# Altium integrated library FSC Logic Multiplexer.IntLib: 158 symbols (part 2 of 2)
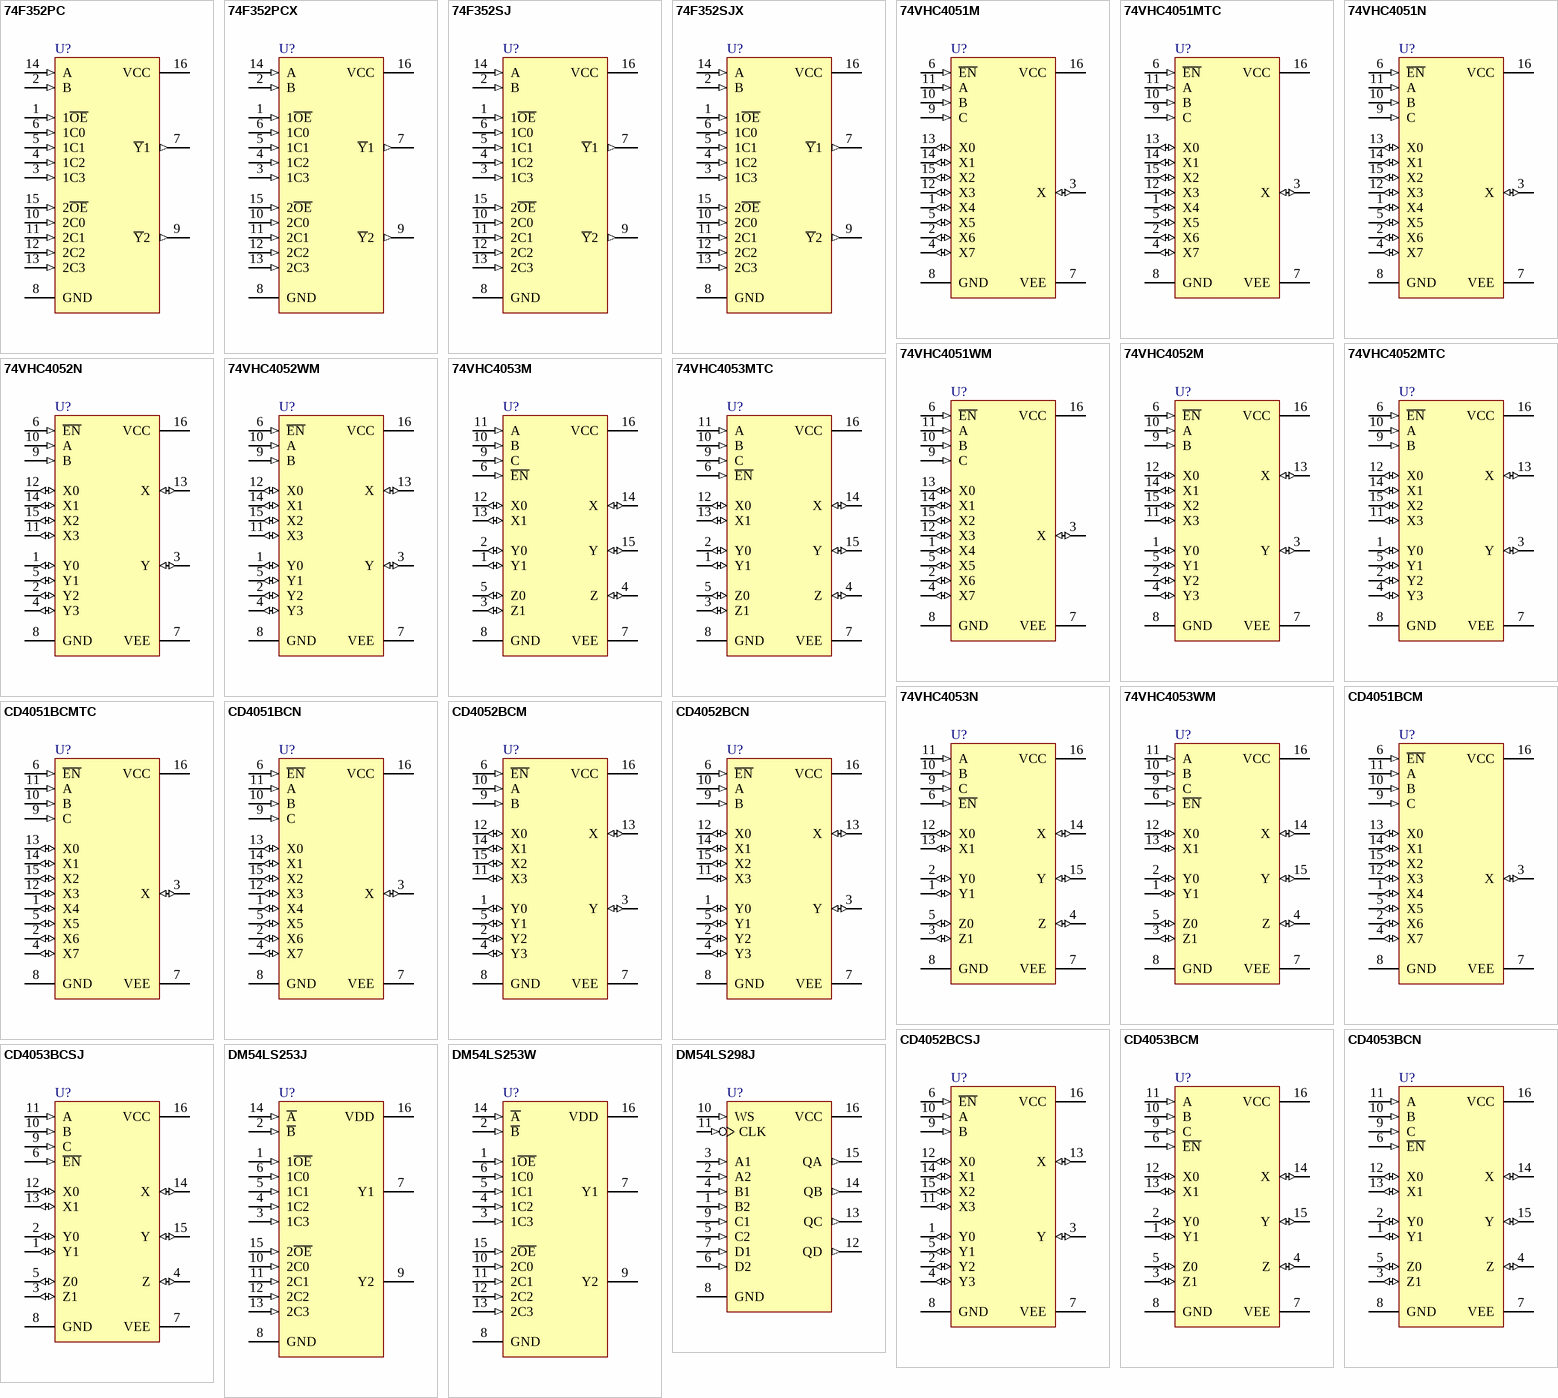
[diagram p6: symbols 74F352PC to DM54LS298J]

## DM54LS253W
designator U?
3-State Data Selector/Multiplexer; Note: Generic simulation model provided.
footprint W16A (DFP; 16 Leads; Body 9.9 x 7.6 mm (LxW max); Pitch 1.27 mm)
3D model W16A (DFP; 16 Leads; Body 9.9 x 7.6 mm (LxW max); Pitch 1.27 mm)
simulation model 74LS253 (SIMCODE)
signal-integrity model DM54LS253W
pins: 1 1~{OE} (in), 2 ~{B} (in), 3 1C3 (in), 4 1C2 (in), 5 1C1 (in), 6 1C0 (in), 7 Y1 (hiz), 8 GND (power), 9 Y2 (hiz), 10 2C0 (in), 11 2C1 (in), 12 2C2 (in), 13 2C3 (in), 14 ~{A} (in), 15 2~{OE} (in), 16 VDD (power)

## DM54LS298J
designator U?
Quad 2-Port Register Multiplexer with Storage; Note: Generic simulation model provided.
footprint J16A (DIP, 16-Leads, Row Spacing 7.62mm, Pitch 2.54mm, Body 19.56x6.73mm)
3D model N16E (CerDIP, 16-Pin, Row Spacing 7.62 mm, Pitch 2.54 mm)
simulation model 74LS298 (SIMCODE)
signal-integrity model DM54LS298J
pins: 1 B2 (in), 2 A2 (in), 3 A1 (in), 4 B1 (in), 5 C2 (in), 6 D2 (in), 7 D1 (in), 8 GND (power), 9 C1 (in), 10 WS (in), 11 CLK (in), 12 QD (out), 13 QC (out), 14 QB (out), 15 QA (out), 16 VCC (power)

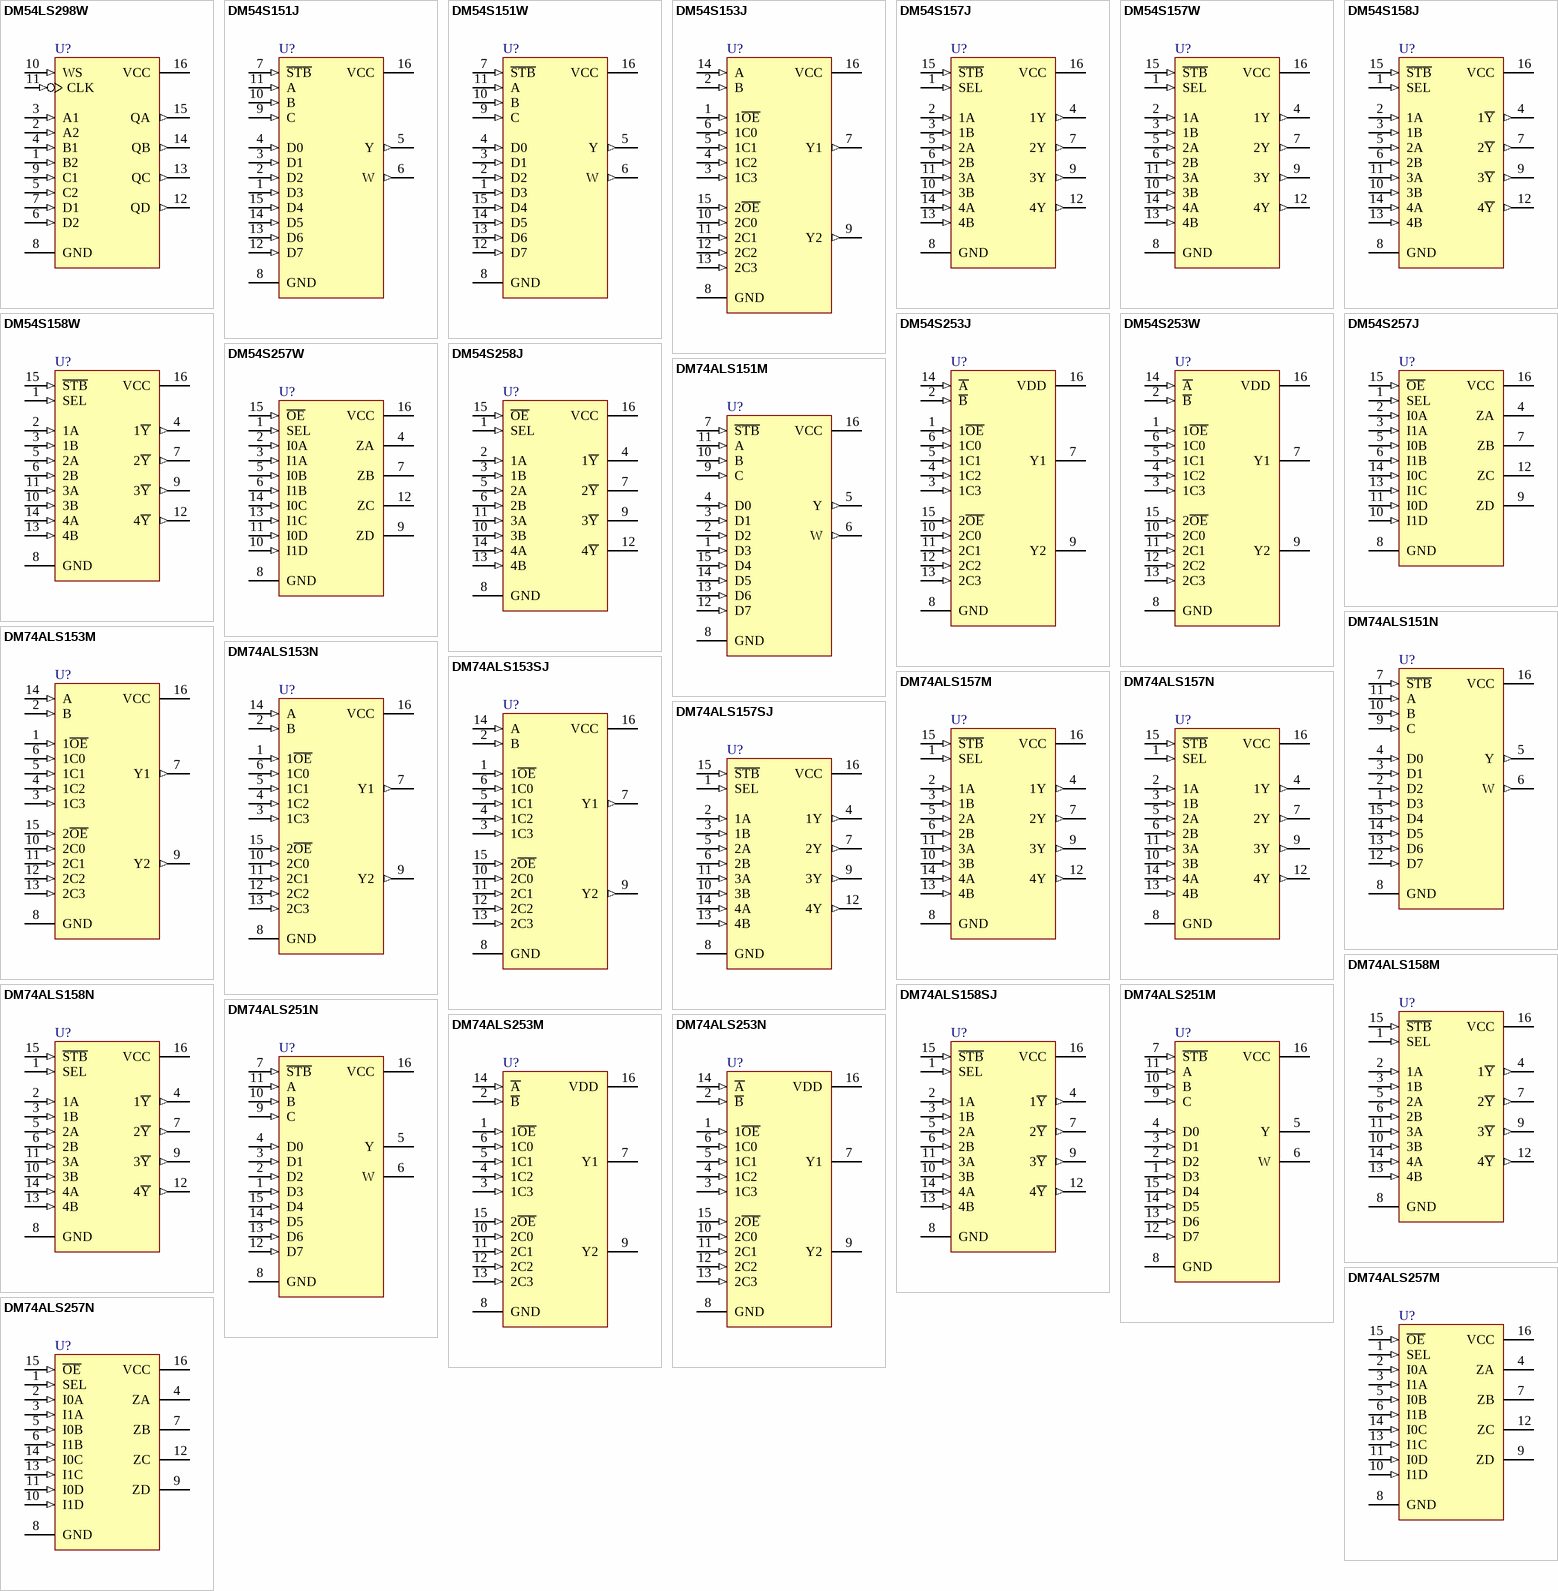
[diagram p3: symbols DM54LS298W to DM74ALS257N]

## DM54LS298W
designator U?
Quad 2-Port Register Multiplexer with Storage; Note: Generic simulation model provided.
footprint W16A (DFP; 16 Leads; Body 9.9 x 7.6 mm (LxW max); Pitch 1.27 mm)
3D model W16A (DFP; 16 Leads; Body 9.9 x 7.6 mm (LxW max); Pitch 1.27 mm)
simulation model 74LS298 (SIMCODE)
signal-integrity model DM54LS298W
pins: 1 B2 (in), 2 A2 (in), 3 A1 (in), 4 B1 (in), 5 C2 (in), 6 D2 (in), 7 D1 (in), 8 GND (power), 9 C1 (in), 10 WS (in), 11 CLK (in), 12 QD (out), 13 QC (out), 14 QB (out), 15 QA (out), 16 VCC (power)

## DM54S151J
designator U?
1 of 8 Data Selector/Multiplexer with Complementary Outputs
footprint J16A (DIP, 16-Leads, Row Spacing 7.62mm, Pitch 2.54mm, Body 19.56x6.73mm)
3D model N16E (CerDIP, 16-Pin, Row Spacing 7.62 mm, Pitch 2.54 mm)
signal-integrity model DM54S151J
pins: 1 D3 (in), 2 D2 (in), 3 D1 (in), 4 D0 (in), 5 Y (out), 6 W (out), 7 ~{STB} (in), 8 GND (power), 9 C (in), 10 B (in), 11 A (in), 12 D7 (in), 13 D6 (in), 14 D5 (in), 15 D4 (in), 16 VCC (power)

## DM54S151W
designator U?
1 of 8 Data Selector/Multiplexer with Complementary Outputs
footprint W16A (DFP; 16 Leads; Body 9.9 x 7.6 mm (LxW max); Pitch 1.27 mm)
3D model W16A (DFP; 16 Leads; Body 9.9 x 7.6 mm (LxW max); Pitch 1.27 mm)
signal-integrity model DM54S151W
pins: 1 D3 (in), 2 D2 (in), 3 D1 (in), 4 D0 (in), 5 Y (out), 6 W (out), 7 ~{STB} (in), 8 GND (power), 9 C (in), 10 B (in), 11 A (in), 12 D7 (in), 13 D6 (in), 14 D5 (in), 15 D4 (in), 16 VCC (power)

## DM54S153J
designator U?
Dual 1 of 4 Line Data Selector/Multiplexer
footprint J16A (DIP, 16-Leads, Row Spacing 7.62mm, Pitch 2.54mm, Body 19.56x6.73mm)
3D model N16E (CerDIP, 16-Pin, Row Spacing 7.62 mm, Pitch 2.54 mm)
signal-integrity model DM54S153J
pins: 1 1~{OE} (in), 2 B (in), 3 1C3 (in), 4 1C2 (in), 5 1C1 (in), 6 1C0 (in), 7 Y1 (out), 8 GND (power), 9 Y2 (out), 10 2C0 (in), 11 2C1 (in), 12 2C2 (in), 13 2C3 (in), 14 A (in), 15 2~{OE} (in), 16 VCC (power)

## DM54S157J
designator U?
Quad 1 of 2 Line Data Selector/Multiplexer; Note: Generic simulation model provided.
footprint J16A (DIP, 16-Leads, Row Spacing 7.62mm, Pitch 2.54mm, Body 19.56x6.73mm)
3D model N16E (CerDIP, 16-Pin, Row Spacing 7.62 mm, Pitch 2.54 mm)
simulation model 74LS157 (SIMCODE)
signal-integrity model DM54S157J
pins: 1 SEL (in), 2 1A (in), 3 1B (in), 4 1Y (out), 5 2A (in), 6 2B (in), 7 2Y (out), 8 GND (power), 9 3Y (out), 10 3B (in), 11 3A (in), 12 4Y (out), 13 4B (in), 14 4A (in), 15 ~{STB} (in), 16 VCC (power)

## DM54S157W
designator U?
Quad 1 of 2 Line Data Selector/Multiplexer; Note: Generic simulation model provided.
footprint W16A (DFP; 16 Leads; Body 9.9 x 7.6 mm (LxW max); Pitch 1.27 mm)
3D model W16A (DFP; 16 Leads; Body 9.9 x 7.6 mm (LxW max); Pitch 1.27 mm)
simulation model 74LS157 (SIMCODE)
signal-integrity model DM54S157W
pins: 1 SEL (in), 2 1A (in), 3 1B (in), 4 1Y (out), 5 2A (in), 6 2B (in), 7 2Y (out), 8 GND (power), 9 3Y (out), 10 3B (in), 11 3A (in), 12 4Y (out), 13 4B (in), 14 4A (in), 15 ~{STB} (in), 16 VCC (power)

## DM54S158J
designator U?
Quad 1 of 2 Line Data Selector/Multiplexer; Note: Generic simulation model provided.
footprint J16A (DIP, 16-Leads, Row Spacing 7.62mm, Pitch 2.54mm, Body 19.56x6.73mm)
3D model N16E (CerDIP, 16-Pin, Row Spacing 7.62 mm, Pitch 2.54 mm)
simulation model 74LS158 (SIMCODE)
signal-integrity model DM54S158J
pins: 1 SEL (in), 2 1A (in), 3 1B (in), 4 1~{Y} (out), 5 2A (in), 6 2B (in), 7 2~{Y} (out), 8 GND (power), 9 3~{Y} (out), 10 3B (in), 11 3A (in), 12 4~{Y} (out), 13 4B (in), 14 4A (in), 15 ~{STB} (in), 16 VCC (power)

## DM54S158W
designator U?
Quad 1 of 2 Line Data Selector/Multiplexer; Note: Generic simulation model provided.
footprint W16A (DFP; 16 Leads; Body 9.9 x 7.6 mm (LxW max); Pitch 1.27 mm)
3D model W16A (DFP; 16 Leads; Body 9.9 x 7.6 mm (LxW max); Pitch 1.27 mm)
simulation model 74LS158 (SIMCODE)
signal-integrity model DM54S158W
pins: 1 SEL (in), 2 1A (in), 3 1B (in), 4 1~{Y} (out), 5 2A (in), 6 2B (in), 7 2~{Y} (out), 8 GND (power), 9 3~{Y} (out), 10 3B (in), 11 3A (in), 12 4~{Y} (out), 13 4B (in), 14 4A (in), 15 ~{STB} (in), 16 VCC (power)

## DM54S253J
designator U?
Dual 3-State 1 of 4 Line Data Selector/Multiplexer; Note: Generic simulation model provided.
footprint J16A (DIP, 16-Leads, Row Spacing 7.62mm, Pitch 2.54mm, Body 19.56x6.73mm)
3D model N16E (CerDIP, 16-Pin, Row Spacing 7.62 mm, Pitch 2.54 mm)
simulation model 74LS253 (SIMCODE)
signal-integrity model DM54S253J
pins: 1 1~{OE} (in), 2 ~{B} (in), 3 1C3 (in), 4 1C2 (in), 5 1C1 (in), 6 1C0 (in), 7 Y1 (hiz), 8 GND (power), 9 Y2 (hiz), 10 2C0 (in), 11 2C1 (in), 12 2C2 (in), 13 2C3 (in), 14 ~{A} (in), 15 2~{OE} (in), 16 VDD (power)

## DM54S253W
designator U?
Dual 3-State 1 of 4 Line Data Selector/Multiplexer; Note: Generic simulation model provided.
footprint W16A (DFP; 16 Leads; Body 9.9 x 7.6 mm (LxW max); Pitch 1.27 mm)
3D model W16A (DFP; 16 Leads; Body 9.9 x 7.6 mm (LxW max); Pitch 1.27 mm)
simulation model 74LS253 (SIMCODE)
signal-integrity model DM54S253W
pins: 1 1~{OE} (in), 2 ~{B} (in), 3 1C3 (in), 4 1C2 (in), 5 1C1 (in), 6 1C0 (in), 7 Y1 (hiz), 8 GND (power), 9 Y2 (hiz), 10 2C0 (in), 11 2C1 (in), 12 2C2 (in), 13 2C3 (in), 14 ~{A} (in), 15 2~{OE} (in), 16 VDD (power)

## DM54S257J
designator U?
3-State Quad 1 of 2 Data Selector/Multiplexer
footprint J16A (DIP, 16-Leads, Row Spacing 7.62mm, Pitch 2.54mm, Body 19.56x6.73mm)
3D model N16E (CerDIP, 16-Pin, Row Spacing 7.62 mm, Pitch 2.54 mm)
signal-integrity model DM54S257J
pins: 1 SEL (in), 2 I0A (in), 3 I1A (in), 4 ZA (hiz), 5 I0B (in), 6 I1B (in), 7 ZB (hiz), 8 GND (power), 9 ZD (hiz), 10 I1D (in), 11 I0D (in), 12 ZC (hiz), 13 I1C (in), 14 I0C (in), 15 ~{OE} (in), 16 VCC (power)

## DM54S257W
designator U?
3-State Quad 1 of 2 Data Selector/Multiplexer
footprint W16A (DFP; 16 Leads; Body 9.9 x 7.6 mm (LxW max); Pitch 1.27 mm)
3D model W16A (DFP; 16 Leads; Body 9.9 x 7.6 mm (LxW max); Pitch 1.27 mm)
signal-integrity model DM54S257W
pins: 1 SEL (in), 2 I0A (in), 3 I1A (in), 4 ZA (hiz), 5 I0B (in), 6 I1B (in), 7 ZB (hiz), 8 GND (power), 9 ZD (hiz), 10 I1D (in), 11 I0D (in), 12 ZC (hiz), 13 I1C (in), 14 I0C (in), 15 ~{OE} (in), 16 VCC (power)

## DM54S258J
designator U?
3-State Quad 1 of 2 Data Selector/Multiplexer; Note: Generic simulation model provided.
footprint J16A (DIP, 16-Leads, Row Spacing 7.62mm, Pitch 2.54mm, Body 19.56x6.73mm)
3D model N16E (CerDIP, 16-Pin, Row Spacing 7.62 mm, Pitch 2.54 mm)
simulation model 74LS258 (SIMCODE)
signal-integrity model DM54S258J
pins: 1 SEL (in), 2 1A (in), 3 1B (in), 4 1~{Y} (hiz), 5 2A (in), 6 2B (in), 7 2~{Y} (hiz), 8 GND (power), 9 3~{Y} (hiz), 10 3B (in), 11 3A (in), 12 4~{Y} (hiz), 13 4B (in), 14 4A (in), 15 ~{OE} (in), 16 VCC (power)

## DM74ALS151M
designator U?
1 of 8 Line Data Selector/Multiplexer
footprint M16A_N (SOIC, 16-Leads, Body 9.9x3.9mm, Pitch 1.27mm, IPC Medium Density)
footprint M16A_L (SOIC, 16-Leads, Body 9.9x3.9mm, Pitch 1.27mm, IPC High Density)
footprint M16A_M (SOIC, 16-Leads, Body 9.9x3.9mm, Pitch 1.27mm, IPC Low Density)
3D model M16A (16-Pin Small Outline Integrated Circuit 1.27 mm Pitch)
signal-integrity model DM74ALS151M
pins: 1 D3 (in), 2 D2 (in), 3 D1 (in), 4 D0 (in), 5 Y (out), 6 W (out), 7 ~{STB} (in), 8 GND (power), 9 C (in), 10 B (in), 11 A (in), 12 D7 (in), 13 D6 (in), 14 D5 (in), 15 D4 (in), 16 VCC (power)

## DM74ALS151N
designator U?
1 of 8 Line Data Selector/Multiplexer
footprint N16A (DIP, 16-Leads, Row Spacing 7.62mm, Pitch 2.54mm, Body 21.76x6.35mm)
3D model N16A (DIP, 16-Pin, Row Spacing 7.62 mm, Pitch 2.54 mm)
signal-integrity model DM74ALS151N
pins: 1 D3 (in), 2 D2 (in), 3 D1 (in), 4 D0 (in), 5 Y (out), 6 W (out), 7 ~{STB} (in), 8 GND (power), 9 C (in), 10 B (in), 11 A (in), 12 D7 (in), 13 D6 (in), 14 D5 (in), 15 D4 (in), 16 VCC (power)

## DM74ALS153M
designator U?
Dual 1 of 4 Line Data Selector/Multiplexer
footprint M16A_N (SOIC, 16-Leads, Body 9.9x3.9mm, Pitch 1.27mm, IPC Medium Density)
footprint M16A_L (SOIC, 16-Leads, Body 9.9x3.9mm, Pitch 1.27mm, IPC High Density)
footprint M16A_M (SOIC, 16-Leads, Body 9.9x3.9mm, Pitch 1.27mm, IPC Low Density)
3D model M16A (16-Pin Small Outline Integrated Circuit 1.27 mm Pitch)
signal-integrity model DM74ALS153M
pins: 1 1~{OE} (in), 2 B (in), 3 1C3 (in), 4 1C2 (in), 5 1C1 (in), 6 1C0 (in), 7 Y1 (out), 8 GND (power), 9 Y2 (out), 10 2C0 (in), 11 2C1 (in), 12 2C2 (in), 13 2C3 (in), 14 A (in), 15 2~{OE} (in), 16 VCC (power)

## DM74ALS153N
designator U?
Dual 1 of 4 Line Data Selector/Multiplexer
footprint N16A (DIP, 16-Leads, Row Spacing 7.62mm, Pitch 2.54mm, Body 21.76x6.35mm)
3D model N16A (DIP, 16-Pin, Row Spacing 7.62 mm, Pitch 2.54 mm)
signal-integrity model DM74ALS153N
pins: 1 1~{OE} (in), 2 B (in), 3 1C3 (in), 4 1C2 (in), 5 1C1 (in), 6 1C0 (in), 7 Y1 (out), 8 GND (power), 9 Y2 (out), 10 2C0 (in), 11 2C1 (in), 12 2C2 (in), 13 2C3 (in), 14 A (in), 15 2~{OE} (in), 16 VCC (power)

## DM74ALS153SJ
designator U?
Dual 1 of 4 Line Data Selector/Multiplexer
footprint M16D_N (SOP, 16-Leads, Body 10.1x5.3mm, Pitch 1.27mm, IPC Medium Density)
footprint M16D_L (SOP, 16-Leads, Body 10.1x5.3mm, Pitch 1.27mm, IPC High Density)
footprint M16D_M (SOP, 16-Leads, Body 10.1x5.3mm, Pitch 1.27mm, IPC Low Density)
3D model M16D (16-Pin Small Outline Package 1.27 mm Pitch)
signal-integrity model DM74ALS153SJ
pins: 1 1~{OE} (in), 2 B (in), 3 1C3 (in), 4 1C2 (in), 5 1C1 (in), 6 1C0 (in), 7 Y1 (out), 8 GND (power), 9 Y2 (out), 10 2C0 (in), 11 2C1 (in), 12 2C2 (in), 13 2C3 (in), 14 A (in), 15 2~{OE} (in), 16 VCC (power)

## DM74ALS157M
designator U?
Quad 1 of 2 Line Data Selector/Multiplexer; Note: Generic simulation model provided.
footprint M16A_N (SOIC, 16-Leads, Body 9.9x3.9mm, Pitch 1.27mm, IPC Medium Density)
footprint M16A_L (SOIC, 16-Leads, Body 9.9x3.9mm, Pitch 1.27mm, IPC High Density)
footprint M16A_M (SOIC, 16-Leads, Body 9.9x3.9mm, Pitch 1.27mm, IPC Low Density)
3D model M16A (16-Pin Small Outline Integrated Circuit 1.27 mm Pitch)
simulation model 74LS157 (SIMCODE)
signal-integrity model DM74ALS157M
pins: 1 SEL (in), 2 1A (in), 3 1B (in), 4 1Y (out), 5 2A (in), 6 2B (in), 7 2Y (out), 8 GND (power), 9 3Y (out), 10 3B (in), 11 3A (in), 12 4Y (out), 13 4B (in), 14 4A (in), 15 ~{STB} (in), 16 VCC (power)

## DM74ALS157N
designator U?
Quad 1 of 2 Line Data Selector/Multiplexer; Note: Generic simulation model provided.
footprint N16A (DIP, 16-Leads, Row Spacing 7.62mm, Pitch 2.54mm, Body 21.76x6.35mm)
3D model N16A (DIP, 16-Pin, Row Spacing 7.62 mm, Pitch 2.54 mm)
simulation model 74LS157 (SIMCODE)
signal-integrity model DM74ALS157N
pins: 1 SEL (in), 2 1A (in), 3 1B (in), 4 1Y (out), 5 2A (in), 6 2B (in), 7 2Y (out), 8 GND (power), 9 3Y (out), 10 3B (in), 11 3A (in), 12 4Y (out), 13 4B (in), 14 4A (in), 15 ~{STB} (in), 16 VCC (power)

## DM74ALS157SJ
designator U?
Quad 1 of 2 Line Data Selector/Multiplexer; Note: Generic simulation model provided.
footprint M16D_N (SOP, 16-Leads, Body 10.1x5.3mm, Pitch 1.27mm, IPC Medium Density)
footprint M16D_L (SOP, 16-Leads, Body 10.1x5.3mm, Pitch 1.27mm, IPC High Density)
footprint M16D_M (SOP, 16-Leads, Body 10.1x5.3mm, Pitch 1.27mm, IPC Low Density)
3D model M16D (16-Pin Small Outline Package 1.27 mm Pitch)
simulation model 74LS157 (SIMCODE)
signal-integrity model DM74ALS157SJ
pins: 1 SEL (in), 2 1A (in), 3 1B (in), 4 1Y (out), 5 2A (in), 6 2B (in), 7 2Y (out), 8 GND (power), 9 3Y (out), 10 3B (in), 11 3A (in), 12 4Y (out), 13 4B (in), 14 4A (in), 15 ~{STB} (in), 16 VCC (power)

## DM74ALS158M
designator U?
Quad 1 of 2 Line Data Selector/Multiplexer; Note: Generic simulation model provided.
footprint M16A_N (SOIC, 16-Leads, Body 9.9x3.9mm, Pitch 1.27mm, IPC Medium Density)
footprint M16A_L (SOIC, 16-Leads, Body 9.9x3.9mm, Pitch 1.27mm, IPC High Density)
footprint M16A_M (SOIC, 16-Leads, Body 9.9x3.9mm, Pitch 1.27mm, IPC Low Density)
3D model M16A (16-Pin Small Outline Integrated Circuit 1.27 mm Pitch)
simulation model 74LS158 (SIMCODE)
signal-integrity model DM74ALS158M
pins: 1 SEL (in), 2 1A (in), 3 1B (in), 4 1~{Y} (out), 5 2A (in), 6 2B (in), 7 2~{Y} (out), 8 GND (power), 9 3~{Y} (out), 10 3B (in), 11 3A (in), 12 4~{Y} (out), 13 4B (in), 14 4A (in), 15 ~{STB} (in), 16 VCC (power)

## DM74ALS158N
designator U?
Quad 1 of 2 Line Data Selector/Multiplexer; Note: Generic simulation model provided.
footprint N16A (DIP, 16-Leads, Row Spacing 7.62mm, Pitch 2.54mm, Body 21.76x6.35mm)
3D model N16A (DIP, 16-Pin, Row Spacing 7.62 mm, Pitch 2.54 mm)
simulation model 74LS158 (SIMCODE)
signal-integrity model DM74ALS158N
pins: 1 SEL (in), 2 1A (in), 3 1B (in), 4 1~{Y} (out), 5 2A (in), 6 2B (in), 7 2~{Y} (out), 8 GND (power), 9 3~{Y} (out), 10 3B (in), 11 3A (in), 12 4~{Y} (out), 13 4B (in), 14 4A (in), 15 ~{STB} (in), 16 VCC (power)

## DM74ALS158SJ
designator U?
Quad 1 of 2 Line Data Selector/Multiplexer; Note: Generic simulation model provided.
footprint M16D_N (SOP, 16-Leads, Body 10.1x5.3mm, Pitch 1.27mm, IPC Medium Density)
footprint M16D_L (SOP, 16-Leads, Body 10.1x5.3mm, Pitch 1.27mm, IPC High Density)
footprint M16D_M (SOP, 16-Leads, Body 10.1x5.3mm, Pitch 1.27mm, IPC Low Density)
3D model M16D (16-Pin Small Outline Package 1.27 mm Pitch)
simulation model 74LS158 (SIMCODE)
signal-integrity model DM74ALS158SJ
pins: 1 SEL (in), 2 1A (in), 3 1B (in), 4 1~{Y} (out), 5 2A (in), 6 2B (in), 7 2~{Y} (out), 8 GND (power), 9 3~{Y} (out), 10 3B (in), 11 3A (in), 12 4~{Y} (out), 13 4B (in), 14 4A (in), 15 ~{STB} (in), 16 VCC (power)

## DM74ALS251M
designator U?
3-State 1 of 8 Line Data Selector/Multiplexer; Note: Generic simulation model provided.
footprint M16A_N (SOIC, 16-Leads, Body 9.9x3.9mm, Pitch 1.27mm, IPC Medium Density)
footprint M16A_L (SOIC, 16-Leads, Body 9.9x3.9mm, Pitch 1.27mm, IPC High Density)
footprint M16A_M (SOIC, 16-Leads, Body 9.9x3.9mm, Pitch 1.27mm, IPC Low Density)
3D model M16A (16-Pin Small Outline Integrated Circuit 1.27 mm Pitch)
simulation model 74LS251 (SIMCODE)
signal-integrity model DM74ALS251M
pins: 1 D3 (in), 2 D2 (in), 3 D1 (in), 4 D0 (in), 5 Y (hiz), 6 W (hiz), 7 ~{STB} (in), 8 GND (power), 9 C (in), 10 B (in), 11 A (in), 12 D7 (in), 13 D6 (in), 14 D5 (in), 15 D4 (in), 16 VCC (power)

## DM74ALS251N
designator U?
3-State 1 of 8 Line Data Selector/Multiplexer; Note: Generic simulation model provided.
footprint N16A (DIP, 16-Leads, Row Spacing 7.62mm, Pitch 2.54mm, Body 21.76x6.35mm)
3D model N16A (DIP, 16-Pin, Row Spacing 7.62 mm, Pitch 2.54 mm)
simulation model 74LS251 (SIMCODE)
signal-integrity model DM74ALS251N
pins: 1 D3 (in), 2 D2 (in), 3 D1 (in), 4 D0 (in), 5 Y (hiz), 6 W (hiz), 7 ~{STB} (in), 8 GND (power), 9 C (in), 10 B (in), 11 A (in), 12 D7 (in), 13 D6 (in), 14 D5 (in), 15 D4 (in), 16 VCC (power)

## DM74ALS253M
designator U?
3-State Dual 1 of 4 Line Data Selector/Multiplexer; Note: Generic simulation model provided.
footprint M16A_N (SOIC, 16-Leads, Body 9.9x3.9mm, Pitch 1.27mm, IPC Medium Density)
footprint M16A_L (SOIC, 16-Leads, Body 9.9x3.9mm, Pitch 1.27mm, IPC High Density)
footprint M16A_M (SOIC, 16-Leads, Body 9.9x3.9mm, Pitch 1.27mm, IPC Low Density)
3D model M16A (16-Pin Small Outline Integrated Circuit 1.27 mm Pitch)
simulation model 74LS253 (SIMCODE)
signal-integrity model DM74ALS253M
pins: 1 1~{OE} (in), 2 ~{B} (in), 3 1C3 (in), 4 1C2 (in), 5 1C1 (in), 6 1C0 (in), 7 Y1 (hiz), 8 GND (power), 9 Y2 (hiz), 10 2C0 (in), 11 2C1 (in), 12 2C2 (in), 13 2C3 (in), 14 ~{A} (in), 15 2~{OE} (in), 16 VDD (power)

## DM74ALS253N
designator U?
3-State Dual 1 of 4 Line Data Selector/Multiplexer; Note: Generic simulation model provided.
footprint N16A (DIP, 16-Leads, Row Spacing 7.62mm, Pitch 2.54mm, Body 21.76x6.35mm)
3D model N16A (DIP, 16-Pin, Row Spacing 7.62 mm, Pitch 2.54 mm)
simulation model 74LS253 (SIMCODE)
signal-integrity model DM74ALS253N
pins: 1 1~{OE} (in), 2 ~{B} (in), 3 1C3 (in), 4 1C2 (in), 5 1C1 (in), 6 1C0 (in), 7 Y1 (hiz), 8 GND (power), 9 Y2 (hiz), 10 2C0 (in), 11 2C1 (in), 12 2C2 (in), 13 2C3 (in), 14 ~{A} (in), 15 2~{OE} (in), 16 VDD (power)

## DM74ALS257M
designator U?
3-State Quad 1 of 2 Line Data Selector/Multiplexer
footprint M16A_N (SOIC, 16-Leads, Body 9.9x3.9mm, Pitch 1.27mm, IPC Medium Density)
footprint M16A_L (SOIC, 16-Leads, Body 9.9x3.9mm, Pitch 1.27mm, IPC High Density)
footprint M16A_M (SOIC, 16-Leads, Body 9.9x3.9mm, Pitch 1.27mm, IPC Low Density)
3D model M16A (16-Pin Small Outline Integrated Circuit 1.27 mm Pitch)
signal-integrity model DM74ALS257M
pins: 1 SEL (in), 2 I0A (in), 3 I1A (in), 4 ZA (hiz), 5 I0B (in), 6 I1B (in), 7 ZB (hiz), 8 GND (power), 9 ZD (hiz), 10 I1D (in), 11 I0D (in), 12 ZC (hiz), 13 I1C (in), 14 I0C (in), 15 ~{OE} (in), 16 VCC (power)

## DM74ALS257N
designator U?
3-State Quad 1 of 2 Line Data Selector/Multiplexer
footprint N16A (DIP, 16-Leads, Row Spacing 7.62mm, Pitch 2.54mm, Body 21.76x6.35mm)
3D model N16A (DIP, 16-Pin, Row Spacing 7.62 mm, Pitch 2.54 mm)
signal-integrity model DM74ALS257N
pins: 1 SEL (in), 2 I0A (in), 3 I1A (in), 4 ZA (hiz), 5 I0B (in), 6 I1B (in), 7 ZB (hiz), 8 GND (power), 9 ZD (hiz), 10 I1D (in), 11 I0D (in), 12 ZC (hiz), 13 I1C (in), 14 I0C (in), 15 ~{OE} (in), 16 VCC (power)

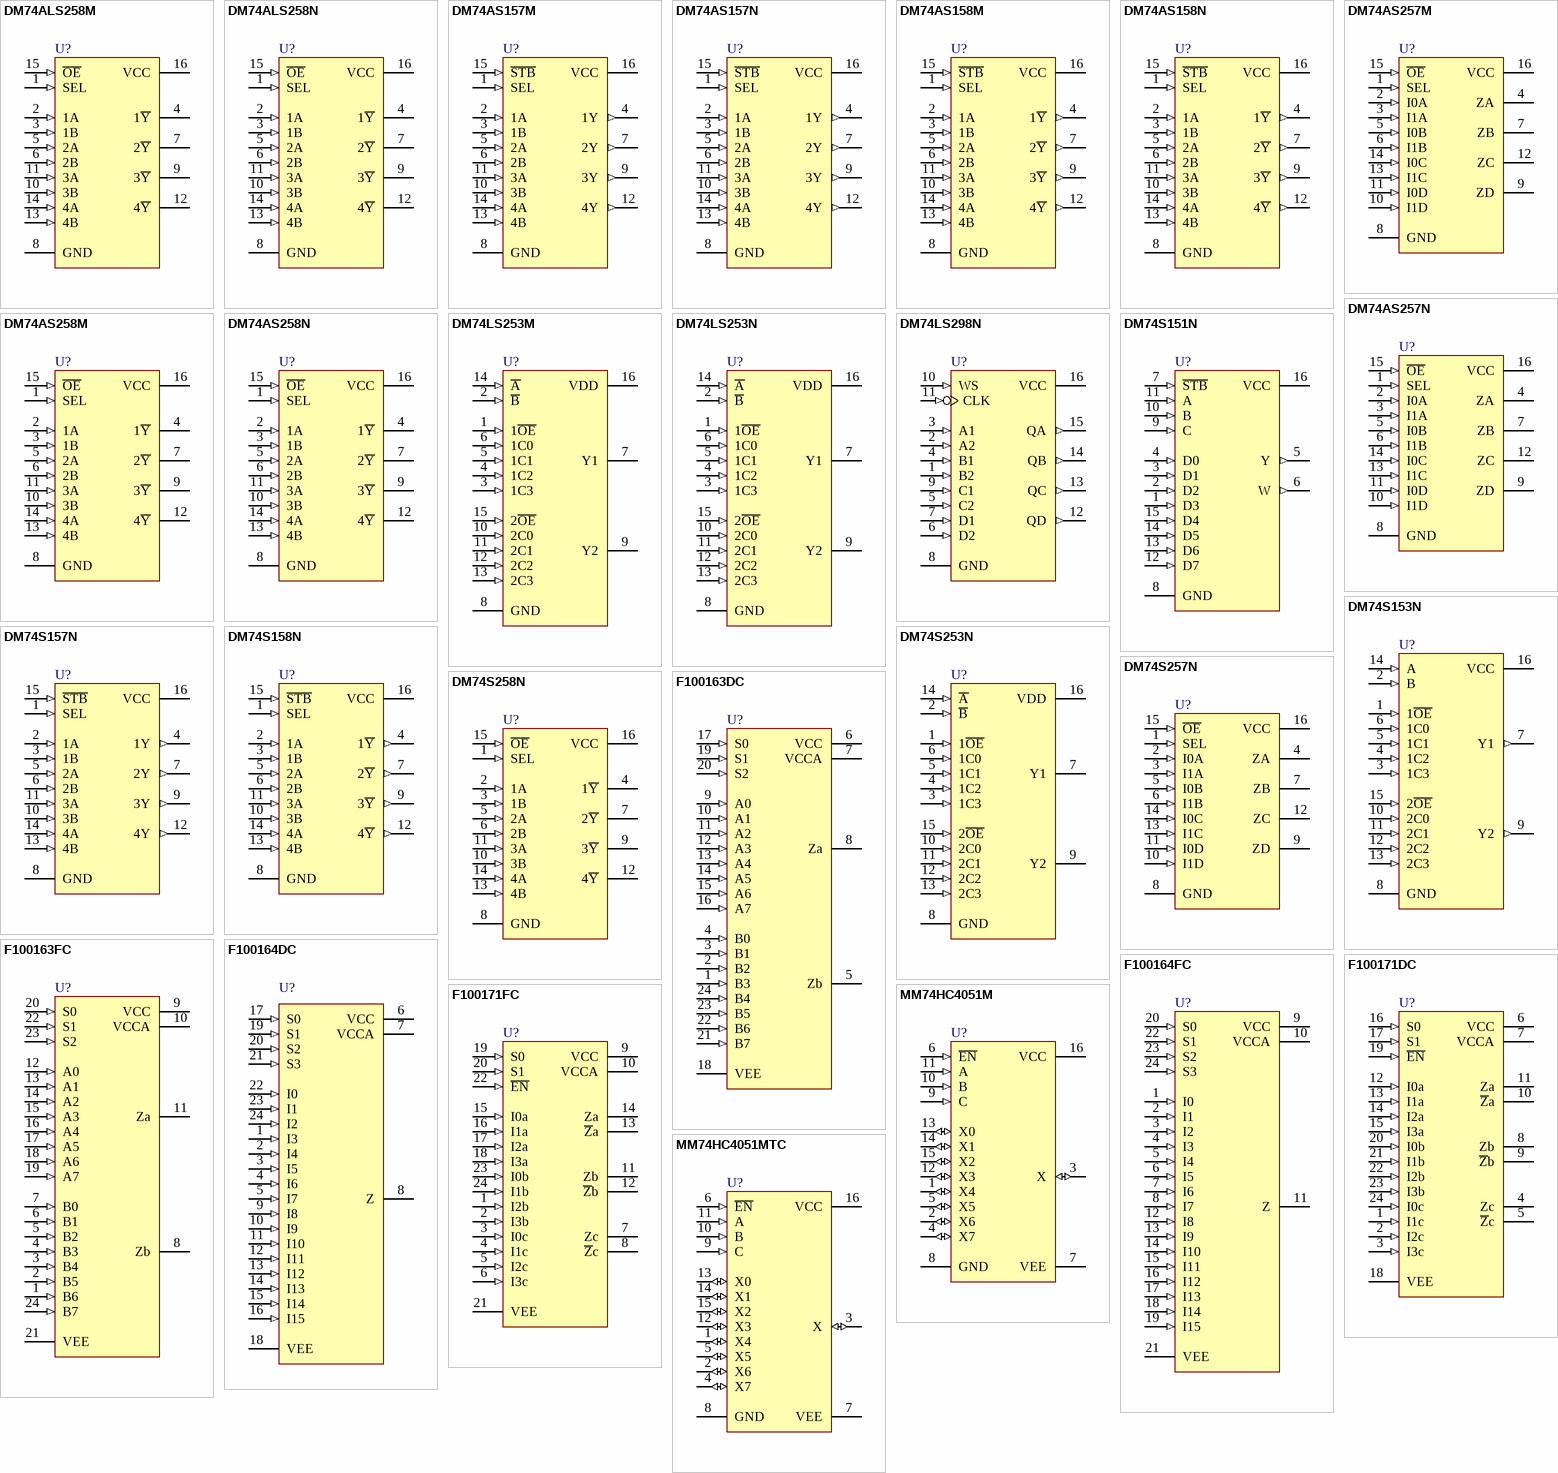
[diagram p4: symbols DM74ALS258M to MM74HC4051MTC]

## DM74ALS258M
designator U?
3-State Quad 1 of 2 Line Data Selector/Multiplexer; Note: Generic simulation model provided.
footprint M16A_N (SOIC, 16-Leads, Body 9.9x3.9mm, Pitch 1.27mm, IPC Medium Density)
footprint M16A_L (SOIC, 16-Leads, Body 9.9x3.9mm, Pitch 1.27mm, IPC High Density)
footprint M16A_M (SOIC, 16-Leads, Body 9.9x3.9mm, Pitch 1.27mm, IPC Low Density)
3D model M16A (16-Pin Small Outline Integrated Circuit 1.27 mm Pitch)
simulation model 74LS258 (SIMCODE)
signal-integrity model DM74ALS258M
pins: 1 SEL (in), 2 1A (in), 3 1B (in), 4 1~{Y} (hiz), 5 2A (in), 6 2B (in), 7 2~{Y} (hiz), 8 GND (power), 9 3~{Y} (hiz), 10 3B (in), 11 3A (in), 12 4~{Y} (hiz), 13 4B (in), 14 4A (in), 15 ~{OE} (in), 16 VCC (power)

## DM74ALS258N
designator U?
3-State Quad 1 of 2 Line Data Selector/Multiplexer; Note: Generic simulation model provided.
footprint N16A (DIP, 16-Leads, Row Spacing 7.62mm, Pitch 2.54mm, Body 21.76x6.35mm)
3D model N16A (DIP, 16-Pin, Row Spacing 7.62 mm, Pitch 2.54 mm)
simulation model 74LS258 (SIMCODE)
signal-integrity model DM74ALS258N
pins: 1 SEL (in), 2 1A (in), 3 1B (in), 4 1~{Y} (hiz), 5 2A (in), 6 2B (in), 7 2~{Y} (hiz), 8 GND (power), 9 3~{Y} (hiz), 10 3B (in), 11 3A (in), 12 4~{Y} (hiz), 13 4B (in), 14 4A (in), 15 ~{OE} (in), 16 VCC (power)

## DM74AS157M
designator U?
Quad 1 of 2 Line Data Selector/Multiplexer; Note: Generic simulation model provided.
footprint M16A_N (SOIC, 16-Leads, Body 9.9x3.9mm, Pitch 1.27mm, IPC Medium Density)
footprint M16A_L (SOIC, 16-Leads, Body 9.9x3.9mm, Pitch 1.27mm, IPC High Density)
footprint M16A_M (SOIC, 16-Leads, Body 9.9x3.9mm, Pitch 1.27mm, IPC Low Density)
3D model M16A (16-Pin Small Outline Integrated Circuit 1.27 mm Pitch)
simulation model 74LS157 (SIMCODE)
signal-integrity model DM74AS157M
pins: 1 SEL (in), 2 1A (in), 3 1B (in), 4 1Y (out), 5 2A (in), 6 2B (in), 7 2Y (out), 8 GND (power), 9 3Y (out), 10 3B (in), 11 3A (in), 12 4Y (out), 13 4B (in), 14 4A (in), 15 ~{STB} (in), 16 VCC (power)

## DM74AS157N
designator U?
Quad 1 of 2 Line Data Selector/Multiplexer; Note: Generic simulation model provided.
footprint N16A (DIP, 16-Leads, Row Spacing 7.62mm, Pitch 2.54mm, Body 21.76x6.35mm)
3D model N16A (DIP, 16-Pin, Row Spacing 7.62 mm, Pitch 2.54 mm)
simulation model 74LS157 (SIMCODE)
signal-integrity model DM74AS157N
pins: 1 SEL (in), 2 1A (in), 3 1B (in), 4 1Y (out), 5 2A (in), 6 2B (in), 7 2Y (out), 8 GND (power), 9 3Y (out), 10 3B (in), 11 3A (in), 12 4Y (out), 13 4B (in), 14 4A (in), 15 ~{STB} (in), 16 VCC (power)

## DM74AS158M
designator U?
Quad 1 of 2 Line Data Selector/Multiplexer; Note: Generic simulation model provided.
footprint M16A_N (SOIC, 16-Leads, Body 9.9x3.9mm, Pitch 1.27mm, IPC Medium Density)
footprint M16A_L (SOIC, 16-Leads, Body 9.9x3.9mm, Pitch 1.27mm, IPC High Density)
footprint M16A_M (SOIC, 16-Leads, Body 9.9x3.9mm, Pitch 1.27mm, IPC Low Density)
3D model M16A (16-Pin Small Outline Integrated Circuit 1.27 mm Pitch)
simulation model 74LS158 (SIMCODE)
signal-integrity model DM74AS158M
pins: 1 SEL (in), 2 1A (in), 3 1B (in), 4 1~{Y} (out), 5 2A (in), 6 2B (in), 7 2~{Y} (out), 8 GND (power), 9 3~{Y} (out), 10 3B (in), 11 3A (in), 12 4~{Y} (out), 13 4B (in), 14 4A (in), 15 ~{STB} (in), 16 VCC (power)

## DM74AS158N
designator U?
Quad 1 of 2 Line Data Selector/Multiplexer; Note: Generic simulation model provided.
footprint N16A (DIP, 16-Leads, Row Spacing 7.62mm, Pitch 2.54mm, Body 21.76x6.35mm)
3D model N16A (DIP, 16-Pin, Row Spacing 7.62 mm, Pitch 2.54 mm)
simulation model 74LS158 (SIMCODE)
signal-integrity model DM74AS158N
pins: 1 SEL (in), 2 1A (in), 3 1B (in), 4 1~{Y} (out), 5 2A (in), 6 2B (in), 7 2~{Y} (out), 8 GND (power), 9 3~{Y} (out), 10 3B (in), 11 3A (in), 12 4~{Y} (out), 13 4B (in), 14 4A (in), 15 ~{STB} (in), 16 VCC (power)

## DM74AS257M
designator U?
3-State Quad 1 of 2 Line Data Selector/Multiplexer
footprint M16A_N (SOIC, 16-Leads, Body 9.9x3.9mm, Pitch 1.27mm, IPC Medium Density)
footprint M16A_L (SOIC, 16-Leads, Body 9.9x3.9mm, Pitch 1.27mm, IPC High Density)
footprint M16A_M (SOIC, 16-Leads, Body 9.9x3.9mm, Pitch 1.27mm, IPC Low Density)
3D model M16A (16-Pin Small Outline Integrated Circuit 1.27 mm Pitch)
signal-integrity model DM74AS257M
pins: 1 SEL (in), 2 I0A (in), 3 I1A (in), 4 ZA (hiz), 5 I0B (in), 6 I1B (in), 7 ZB (hiz), 8 GND (power), 9 ZD (hiz), 10 I1D (in), 11 I0D (in), 12 ZC (hiz), 13 I1C (in), 14 I0C (in), 15 ~{OE} (in), 16 VCC (power)

## DM74AS257N
designator U?
3-State Quad 1 of 2 Line Data Selector/Multiplexer
footprint N16A (DIP, 16-Leads, Row Spacing 7.62mm, Pitch 2.54mm, Body 21.76x6.35mm)
3D model N16A (DIP, 16-Pin, Row Spacing 7.62 mm, Pitch 2.54 mm)
signal-integrity model DM74AS257N
pins: 1 SEL (in), 2 I0A (in), 3 I1A (in), 4 ZA (hiz), 5 I0B (in), 6 I1B (in), 7 ZB (hiz), 8 GND (power), 9 ZD (hiz), 10 I1D (in), 11 I0D (in), 12 ZC (hiz), 13 I1C (in), 14 I0C (in), 15 ~{OE} (in), 16 VCC (power)

## DM74AS258M
designator U?
3-State Quad 1 of 2 Line Data Selector/Multiplexer; Note: Generic simulation model provided.
footprint M16A_N (SOIC, 16-Leads, Body 9.9x3.9mm, Pitch 1.27mm, IPC Medium Density)
footprint M16A_L (SOIC, 16-Leads, Body 9.9x3.9mm, Pitch 1.27mm, IPC High Density)
footprint M16A_M (SOIC, 16-Leads, Body 9.9x3.9mm, Pitch 1.27mm, IPC Low Density)
3D model M16A (16-Pin Small Outline Integrated Circuit 1.27 mm Pitch)
simulation model 74LS258 (SIMCODE)
signal-integrity model DM74AS258M
pins: 1 SEL (in), 2 1A (in), 3 1B (in), 4 1~{Y} (hiz), 5 2A (in), 6 2B (in), 7 2~{Y} (hiz), 8 GND (power), 9 3~{Y} (hiz), 10 3B (in), 11 3A (in), 12 4~{Y} (hiz), 13 4B (in), 14 4A (in), 15 ~{OE} (in), 16 VCC (power)

## DM74AS258N
designator U?
3-State Quad 1 of 2 Line Data Selector/Multiplexer; Note: Generic simulation model provided.
footprint N16A (DIP, 16-Leads, Row Spacing 7.62mm, Pitch 2.54mm, Body 21.76x6.35mm)
3D model N16A (DIP, 16-Pin, Row Spacing 7.62 mm, Pitch 2.54 mm)
simulation model 74LS258 (SIMCODE)
signal-integrity model DM74AS258N
pins: 1 SEL (in), 2 1A (in), 3 1B (in), 4 1~{Y} (hiz), 5 2A (in), 6 2B (in), 7 2~{Y} (hiz), 8 GND (power), 9 3~{Y} (hiz), 10 3B (in), 11 3A (in), 12 4~{Y} (hiz), 13 4B (in), 14 4A (in), 15 ~{OE} (in), 16 VCC (power)

## DM74LS253M
designator U?
3-State Data Selector/Multiplexer; Note: Generic simulation model provided.
footprint M16A_N (SOIC, 16-Leads, Body 9.9x3.9mm, Pitch 1.27mm, IPC Medium Density)
footprint M16A_L (SOIC, 16-Leads, Body 9.9x3.9mm, Pitch 1.27mm, IPC High Density)
footprint M16A_M (SOIC, 16-Leads, Body 9.9x3.9mm, Pitch 1.27mm, IPC Low Density)
3D model M16A (16-Pin Small Outline Integrated Circuit 1.27 mm Pitch)
simulation model 74LS253 (SIMCODE)
signal-integrity model DM74LS253M
pins: 1 1~{OE} (in), 2 ~{B} (in), 3 1C3 (in), 4 1C2 (in), 5 1C1 (in), 6 1C0 (in), 7 Y1 (hiz), 8 GND (power), 9 Y2 (hiz), 10 2C0 (in), 11 2C1 (in), 12 2C2 (in), 13 2C3 (in), 14 ~{A} (in), 15 2~{OE} (in), 16 VDD (power)

## DM74LS253N
designator U?
3-State Data Selector/Multiplexer; Note: Generic simulation model provided.
footprint N16E (DIP, 16-Leads, Row Spacing 7.62mm, Pitch 2.54mm, Body 19.3x6.35mm)
3D model N16E (DIP, 16-Pin, Row Spacing 7.62 mm, Pitch 2.54 mm)
simulation model 74LS253 (SIMCODE)
signal-integrity model DM74LS253N
pins: 1 1~{OE} (in), 2 ~{B} (in), 3 1C3 (in), 4 1C2 (in), 5 1C1 (in), 6 1C0 (in), 7 Y1 (hiz), 8 GND (power), 9 Y2 (hiz), 10 2C0 (in), 11 2C1 (in), 12 2C2 (in), 13 2C3 (in), 14 ~{A} (in), 15 2~{OE} (in), 16 VDD (power)

## DM74LS298N
designator U?
Quad 2-Port Register Multiplexer with Storage; Note: Generic simulation model provided.
footprint N16E (DIP, 16-Leads, Row Spacing 7.62mm, Pitch 2.54mm, Body 19.3x6.35mm)
3D model N16E (DIP, 16-Pin, Row Spacing 7.62 mm, Pitch 2.54 mm)
simulation model 74LS298 (SIMCODE)
signal-integrity model DM74LS298N
pins: 1 B2 (in), 2 A2 (in), 3 A1 (in), 4 B1 (in), 5 C2 (in), 6 D2 (in), 7 D1 (in), 8 GND (power), 9 C1 (in), 10 WS (in), 11 CLK (in), 12 QD (out), 13 QC (out), 14 QB (out), 15 QA (out), 16 VCC (power)

## DM74S151N
designator U?
1 of 8 Data Selector/Multiplexer with Complementary Outputs
footprint N16E (DIP, 16-Leads, Row Spacing 7.62mm, Pitch 2.54mm, Body 19.3x6.35mm)
3D model N16E (DIP, 16-Pin, Row Spacing 7.62 mm, Pitch 2.54 mm)
signal-integrity model DM74S151N
pins: 1 D3 (in), 2 D2 (in), 3 D1 (in), 4 D0 (in), 5 Y (out), 6 W (out), 7 ~{STB} (in), 8 GND (power), 9 C (in), 10 B (in), 11 A (in), 12 D7 (in), 13 D6 (in), 14 D5 (in), 15 D4 (in), 16 VCC (power)

## DM74S153N
designator U?
Dual 1 of 4 Line Data Selector/Multiplexer
footprint N16E (DIP, 16-Leads, Row Spacing 7.62mm, Pitch 2.54mm, Body 19.3x6.35mm)
3D model N16E (DIP, 16-Pin, Row Spacing 7.62 mm, Pitch 2.54 mm)
signal-integrity model DM74S153N
pins: 1 1~{OE} (in), 2 B (in), 3 1C3 (in), 4 1C2 (in), 5 1C1 (in), 6 1C0 (in), 7 Y1 (out), 8 GND (power), 9 Y2 (out), 10 2C0 (in), 11 2C1 (in), 12 2C2 (in), 13 2C3 (in), 14 A (in), 15 2~{OE} (in), 16 VCC (power)

## DM74S157N
designator U?
Quad 1 of 2 Line Data Selector/Multiplexer; Note: Generic simulation model provided.
footprint N16E (DIP, 16-Leads, Row Spacing 7.62mm, Pitch 2.54mm, Body 19.3x6.35mm)
3D model N16E (DIP, 16-Pin, Row Spacing 7.62 mm, Pitch 2.54 mm)
simulation model 74LS157 (SIMCODE)
signal-integrity model DM74S157N
pins: 1 SEL (in), 2 1A (in), 3 1B (in), 4 1Y (out), 5 2A (in), 6 2B (in), 7 2Y (out), 8 GND (power), 9 3Y (out), 10 3B (in), 11 3A (in), 12 4Y (out), 13 4B (in), 14 4A (in), 15 ~{STB} (in), 16 VCC (power)

## DM74S158N
designator U?
Quad 1 of 2 Line Data Selector/Multiplexer; Note: Generic simulation model provided.
footprint N16E (DIP, 16-Leads, Row Spacing 7.62mm, Pitch 2.54mm, Body 19.3x6.35mm)
3D model N16E (DIP, 16-Pin, Row Spacing 7.62 mm, Pitch 2.54 mm)
simulation model 74LS158 (SIMCODE)
signal-integrity model DM74S158N
pins: 1 SEL (in), 2 1A (in), 3 1B (in), 4 1~{Y} (out), 5 2A (in), 6 2B (in), 7 2~{Y} (out), 8 GND (power), 9 3~{Y} (out), 10 3B (in), 11 3A (in), 12 4~{Y} (out), 13 4B (in), 14 4A (in), 15 ~{STB} (in), 16 VCC (power)

## DM74S253N
designator U?
Dual 3-State 1 of 4 Line Data Selector/Multiplexer; Note: Generic simulation model provided.
footprint N16E (DIP, 16-Leads, Row Spacing 7.62mm, Pitch 2.54mm, Body 19.3x6.35mm)
3D model N16E (DIP, 16-Pin, Row Spacing 7.62 mm, Pitch 2.54 mm)
simulation model 74LS253 (SIMCODE)
signal-integrity model DM74S253N
pins: 1 1~{OE} (in), 2 ~{B} (in), 3 1C3 (in), 4 1C2 (in), 5 1C1 (in), 6 1C0 (in), 7 Y1 (hiz), 8 GND (power), 9 Y2 (hiz), 10 2C0 (in), 11 2C1 (in), 12 2C2 (in), 13 2C3 (in), 14 ~{A} (in), 15 2~{OE} (in), 16 VDD (power)

## DM74S257N
designator U?
3-State Quad 1 of 2 Data Selector/Multiplexer
footprint N16E (DIP, 16-Leads, Row Spacing 7.62mm, Pitch 2.54mm, Body 19.3x6.35mm)
3D model N16E (DIP, 16-Pin, Row Spacing 7.62 mm, Pitch 2.54 mm)
signal-integrity model DM74S257N
pins: 1 SEL (in), 2 I0A (in), 3 I1A (in), 4 ZA (hiz), 5 I0B (in), 6 I1B (in), 7 ZB (hiz), 8 GND (power), 9 ZD (hiz), 10 I1D (in), 11 I0D (in), 12 ZC (hiz), 13 I1C (in), 14 I0C (in), 15 ~{OE} (in), 16 VCC (power)

## DM74S258N
designator U?
3-State Quad 1 of 2 Data Selector/Multiplexer; Note: Generic simulation model provided.
footprint N16E (DIP, 16-Leads, Row Spacing 7.62mm, Pitch 2.54mm, Body 19.3x6.35mm)
3D model N16E (DIP, 16-Pin, Row Spacing 7.62 mm, Pitch 2.54 mm)
simulation model 74LS258 (SIMCODE)
signal-integrity model DM74S258N
pins: 1 SEL (in), 2 1A (in), 3 1B (in), 4 1~{Y} (hiz), 5 2A (in), 6 2B (in), 7 2~{Y} (hiz), 8 GND (power), 9 3~{Y} (hiz), 10 3B (in), 11 3A (in), 12 4~{Y} (hiz), 13 4B (in), 14 4A (in), 15 ~{OE} (in), 16 VCC (power)

## F100163DC
designator U?
Dual 8-Input Multiplexer
footprint 6Y (DIP, 24-Leads, Row Spacing 10.16mm, Pitch 2.54mm, Body 30.57x9.89mm)
3D model 6Y (DIP, 24-Pin, Row Spacing 10.16 mm, Pitch 2.54 mm)
pins: 1 B3 (in), 2 B2 (in), 3 B1 (in), 4 B0 (in), 5 Zb (oe), 6 VCC (power), 7 VCCA (power), 8 Za (oe), 9 A0 (in), 10 A1 (in), 11 A2 (in), 12 A3 (in), 13 A4 (in), 14 A5 (in), 15 A6 (in), 16 A7 (in), 17 S0 (in), 18 VEE (power), 19 S1 (in), 20 S2 (in), 21 B7 (in), 22 B6 (in), 23 B5 (in), 24 B4 (in)
1 alternate drawing of the same symbol

## F100163FC
designator U?
Dual 8-Input Multiplexer
footprint 4V_N (CQFP, 24-Leads, Body 10x10mm; Pitch 1.27mm, Gullwing Leadform, IPC Medium Density)
footprint 4V_L (CQFP, 24-Leads, Body 10x10mm; Pitch 1.27mm, Gullwing Leadform, IPC High Density)
footprint 4V_M (CQFP, 24-Leads, Body 10x10mm; Pitch 1.27mm, Gullwing Leadform, IPC Low Density)
3D model F100163-4V (100-Pin Quad Cerpak 1.27 mm Pitch)
pins: 1 B6 (in), 2 B5 (in), 3 B4 (in), 4 B3 (in), 5 B2 (in), 6 B1 (in), 7 B0 (in), 8 Zb (oe), 9 VCC (power), 10 VCCA (power), 11 Za (oe), 12 A0 (in), 13 A1 (in), 14 A2 (in), 15 A3 (in), 16 A4 (in), 17 A5 (in), 18 A6 (in), 19 A7 (in), 20 S0 (in), 21 VEE (power), 22 S1 (in), 23 S2 (in), 24 B7 (in)

## F100164DC
designator U?
16-Input Multiplexer
footprint 6Y (DIP, 24-Leads, Row Spacing 10.16mm, Pitch 2.54mm, Body 30.57x9.89mm)
3D model 6Y (DIP, 24-Pin, Row Spacing 10.16 mm, Pitch 2.54 mm)
pins: 1 I3 (in), 2 I4 (in), 3 I5 (in), 4 I6 (in), 5 I7 (in), 6 VCC (power), 7 VCCA (power), 8 Z (oe), 9 I8 (in), 10 I9 (in), 11 I10 (in), 12 I11 (in), 13 I12 (in), 14 I13 (in), 15 I14 (in), 16 I15 (in), 17 S0 (in), 18 VEE (power), 19 S1 (in), 20 S2 (in), 21 S3 (in), 22 I0 (in), 23 I1 (in), 24 I2 (in)
1 alternate drawing of the same symbol

## F100164FC
designator U?
16-Input Multiplexer
footprint 4V_N (CQFP, 24-Leads, Body 10x10mm; Pitch 1.27mm, Gullwing Leadform, IPC Medium Density)
footprint 4V_L (CQFP, 24-Leads, Body 10x10mm; Pitch 1.27mm, Gullwing Leadform, IPC High Density)
footprint 4V_M (CQFP, 24-Leads, Body 10x10mm; Pitch 1.27mm, Gullwing Leadform, IPC Low Density)
3D model F100164-4V (100-Pin Quad Cerpak 1.27 mm Pitch)
pins: 1 I0 (in), 2 I1 (in), 3 I2 (in), 4 I3 (in), 5 I4 (in), 6 I5 (in), 7 I6 (in), 8 I7 (in), 9 VCC (power), 10 VCCA (power), 11 Z (oe), 12 I8 (in), 13 I9 (in), 14 I10 (in), 15 I11 (in), 16 I12 (in), 17 I13 (in), 18 I14 (in), 19 I15 (in), 20 S0 (in), 21 VEE (power), 22 S1 (in), 23 S2 (in), 24 S3 (in)

## F100171DC
designator U?
Triple 4-Input Multiplexer with Enable
footprint 6Y (DIP, 24-Leads, Row Spacing 10.16mm, Pitch 2.54mm, Body 30.57x9.89mm)
3D model 6Y (DIP, 24-Pin, Row Spacing 10.16 mm, Pitch 2.54 mm)
pins: 1 I1c (in), 2 I2c (in), 3 I3c (in), 4 Zc (oe), 5 ~{Z}c (oe), 6 VCC (power), 7 VCCA (power), 8 Zb (oe), 9 ~{Z}b (oe), 10 ~{Z}a (oe), 11 Za (oe), 12 I0a (in), 13 I1a (in), 14 I2a (in), 15 I3a (in), 16 S0 (in), 17 S1 (in), 18 VEE (power), 19 ~{EN} (in), 20 I0b (in), 21 I1b (in), 22 I2b (in), 23 I3b (in), 24 I0c (in)

## F100171FC
designator U?
Triple 4-Input Multiplexer with Enable
footprint 4V_N (CQFP, 24-Leads, Body 10x10mm; Pitch 1.27mm, Gullwing Leadform, IPC Medium Density)
footprint 4V_L (CQFP, 24-Leads, Body 10x10mm; Pitch 1.27mm, Gullwing Leadform, IPC High Density)
footprint 4V_M (CQFP, 24-Leads, Body 10x10mm; Pitch 1.27mm, Gullwing Leadform, IPC Low Density)
3D model F100171-4V (100-Pin Quad Cerpak 1.27 mm Pitch)
pins: 1 I2b (in), 2 I3b (in), 3 I0c (in), 4 I1c (in), 5 I2c (in), 6 I3c (in), 7 Zc (oe), 8 ~{Z}c (oe), 9 VCC (power), 10 VCCA (power), 11 Zb (oe), 12 ~{Z}b (oe), 13 ~{Z}a (oe), 14 Za (oe), 15 I0a (in), 16 I1a (in), 17 I2a (in), 18 I3a (in), 19 S0 (in), 20 S1 (in), 21 VEE (power), 22 ~{EN} (in), 23 I0b (in), 24 I1b (in)

## MM74HC4051M
designator U?
8-Channel Analog Multiplexer
footprint M16A_N (SOIC, 16-Leads, Body 9.9x3.9mm, Pitch 1.27mm, IPC Medium Density)
footprint M16A_L (SOIC, 16-Leads, Body 9.9x3.9mm, Pitch 1.27mm, IPC High Density)
footprint M16A_M (SOIC, 16-Leads, Body 9.9x3.9mm, Pitch 1.27mm, IPC Low Density)
3D model M16A (16-Pin Small Outline Integrated Circuit 1.27 mm Pitch)
signal-integrity model MM74HC4051M
pins: 1 X4 (io), 2 X6 (io), 3 X (io), 4 X7 (io), 5 X5 (io), 6 ~{EN} (in), 7 VEE (power), 8 GND (power), 9 C (in), 10 B (in), 11 A (in), 12 X3 (io), 13 X0 (io), 14 X1 (io), 15 X2 (io), 16 VCC (power)

## MM74HC4051MTC
designator U?
8-Channel Analog Multiplexer
footprint MTC16_N (TSOP, 16-Leads, Body 5x4.4mm, Pitch 0.65mm, IPC Medium Density)
footprint MTC16_L (TSOP, 16-Leads, Body 5x4.4mm, Pitch 0.65mm, IPC High Density)
footprint MTC16_M (TSOP, 16-Leads, Body 5x4.4mm, Pitch 0.65mm, IPC Low Density)
3D model MTC16 (16-Pin Thin Small Outline Package 0.65 mm Pitch)
signal-integrity model MM74HC4051MTC
pins: 1 X4 (io), 2 X6 (io), 3 X (io), 4 X7 (io), 5 X5 (io), 6 ~{EN} (in), 7 VEE (power), 8 GND (power), 9 C (in), 10 B (in), 11 A (in), 12 X3 (io), 13 X0 (io), 14 X1 (io), 15 X2 (io), 16 VCC (power)

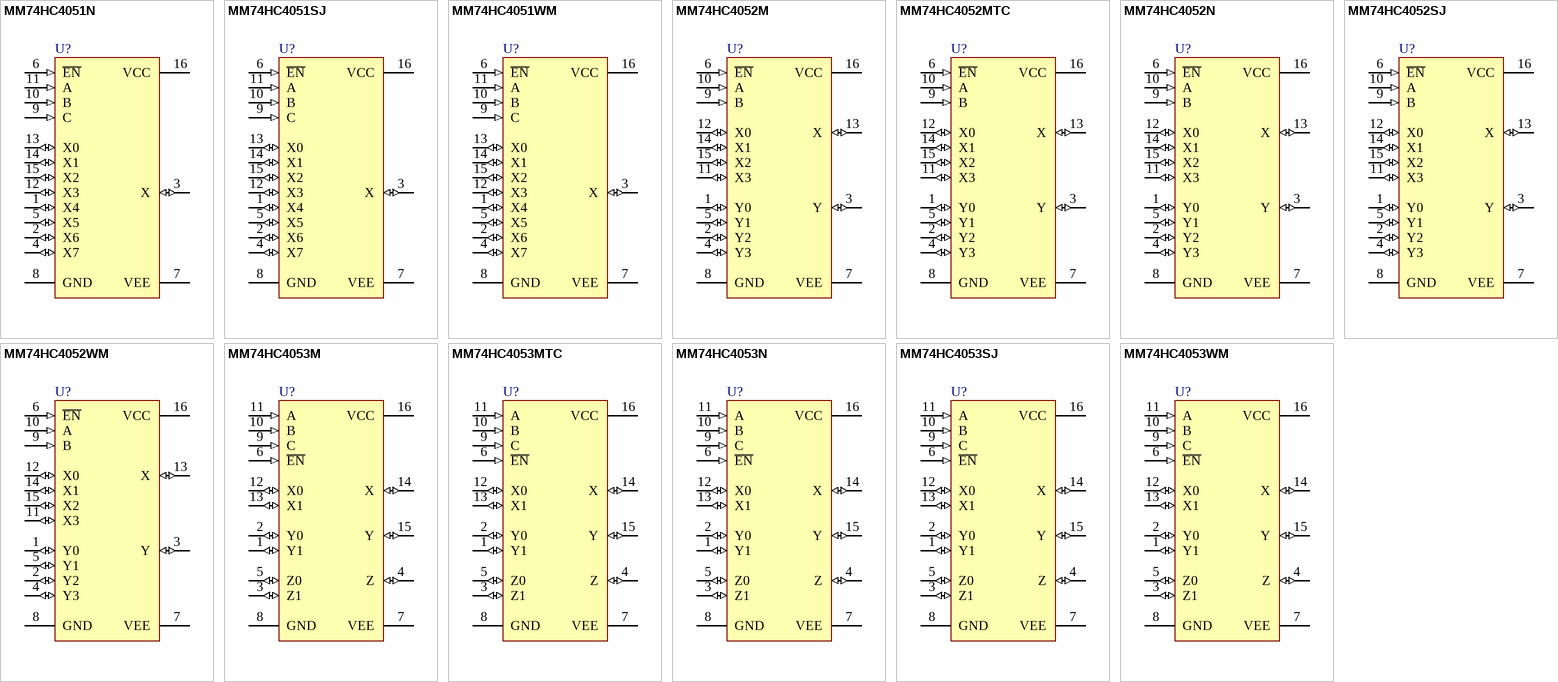
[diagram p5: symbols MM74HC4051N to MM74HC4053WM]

## MM74HC4051N
designator U?
8-Channel Analog Multiplexer
footprint N16E (DIP, 16-Leads, Row Spacing 7.62mm, Pitch 2.54mm, Body 19.3x6.35mm)
3D model N16E (DIP, 16-Pin, Row Spacing 7.62 mm, Pitch 2.54 mm)
signal-integrity model MM74HC4051N
pins: 1 X4 (io), 2 X6 (io), 3 X (io), 4 X7 (io), 5 X5 (io), 6 ~{EN} (in), 7 VEE (power), 8 GND (power), 9 C (in), 10 B (in), 11 A (in), 12 X3 (io), 13 X0 (io), 14 X1 (io), 15 X2 (io), 16 VCC (power)

## MM74HC4051SJ
designator U?
8-Channel Analog Multiplexer
footprint M16D_N (SOP, 16-Leads, Body 10.1x5.3mm, Pitch 1.27mm, IPC Medium Density)
footprint M16D_L (SOP, 16-Leads, Body 10.1x5.3mm, Pitch 1.27mm, IPC High Density)
footprint M16D_M (SOP, 16-Leads, Body 10.1x5.3mm, Pitch 1.27mm, IPC Low Density)
3D model M16D (16-Pin Small Outline Package 1.27 mm Pitch)
signal-integrity model MM74HC4051SJ
pins: 1 X4 (io), 2 X6 (io), 3 X (io), 4 X7 (io), 5 X5 (io), 6 ~{EN} (in), 7 VEE (power), 8 GND (power), 9 C (in), 10 B (in), 11 A (in), 12 X3 (io), 13 X0 (io), 14 X1 (io), 15 X2 (io), 16 VCC (power)

## MM74HC4051WM
designator U?
8-Channel Analog Multiplexer
footprint M16B_N (SOIC, 16-Leads, Body 10.3x7.5mm, Pitch 1.27mm, IPC Medium Density)
footprint M16B_L (SOIC, 16-Leads, Body 10.3x7.5mm, Pitch 1.27mm, IPC High Density)
footprint M16B_M (SOIC, 16-Leads, Body 10.3x7.5mm, Pitch 1.27mm, IPC Low Density)
3D model M16B (16-Pin Small Outline Integrated Circuit 1.27 mm Pitch)
signal-integrity model MM74HC4051WM
pins: 1 X4 (io), 2 X6 (io), 3 X (io), 4 X7 (io), 5 X5 (io), 6 ~{EN} (in), 7 VEE (power), 8 GND (power), 9 C (in), 10 B (in), 11 A (in), 12 X3 (io), 13 X0 (io), 14 X1 (io), 15 X2 (io), 16 VCC (power)

## MM74HC4052M
designator U?
Dual 4-Channel Analog Multiplexer
footprint M16A_N (SOIC, 16-Leads, Body 9.9x3.9mm, Pitch 1.27mm, IPC Medium Density)
footprint M16A_L (SOIC, 16-Leads, Body 9.9x3.9mm, Pitch 1.27mm, IPC High Density)
footprint M16A_M (SOIC, 16-Leads, Body 9.9x3.9mm, Pitch 1.27mm, IPC Low Density)
3D model M16A (16-Pin Small Outline Integrated Circuit 1.27 mm Pitch)
signal-integrity model MM74HC4052M
pins: 1 Y0 (io), 2 Y2 (io), 3 Y (io), 4 Y3 (io), 5 Y1 (io), 6 ~{EN} (in), 7 VEE (power), 8 GND (power), 9 B (in), 10 A (in), 11 X3 (io), 12 X0 (io), 13 X (io), 14 X1 (io), 15 X2 (io), 16 VCC (power)

## MM74HC4052MTC
designator U?
Dual 4-Channel Analog Multiplexer
footprint MTC16_N (TSOP, 16-Leads, Body 5x4.4mm, Pitch 0.65mm, IPC Medium Density)
footprint MTC16_L (TSOP, 16-Leads, Body 5x4.4mm, Pitch 0.65mm, IPC High Density)
footprint MTC16_M (TSOP, 16-Leads, Body 5x4.4mm, Pitch 0.65mm, IPC Low Density)
3D model MTC16 (16-Pin Thin Small Outline Package 0.65 mm Pitch)
signal-integrity model MM74HC4052MTC
pins: 1 Y0 (io), 2 Y2 (io), 3 Y (io), 4 Y3 (io), 5 Y1 (io), 6 ~{EN} (in), 7 VEE (power), 8 GND (power), 9 B (in), 10 A (in), 11 X3 (io), 12 X0 (io), 13 X (io), 14 X1 (io), 15 X2 (io), 16 VCC (power)

## MM74HC4052N
designator U?
Dual 4-Channel Analog Multiplexer
footprint N16E (DIP, 16-Leads, Row Spacing 7.62mm, Pitch 2.54mm, Body 19.3x6.35mm)
3D model N16E (DIP, 16-Pin, Row Spacing 7.62 mm, Pitch 2.54 mm)
signal-integrity model MM74HC4052N
pins: 1 Y0 (io), 2 Y2 (io), 3 Y (io), 4 Y3 (io), 5 Y1 (io), 6 ~{EN} (in), 7 VEE (power), 8 GND (power), 9 B (in), 10 A (in), 11 X3 (io), 12 X0 (io), 13 X (io), 14 X1 (io), 15 X2 (io), 16 VCC (power)

## MM74HC4052SJ
designator U?
Dual 4-Channel Analog Multiplexer
footprint M16D_N (SOP, 16-Leads, Body 10.1x5.3mm, Pitch 1.27mm, IPC Medium Density)
footprint M16D_L (SOP, 16-Leads, Body 10.1x5.3mm, Pitch 1.27mm, IPC High Density)
footprint M16D_M (SOP, 16-Leads, Body 10.1x5.3mm, Pitch 1.27mm, IPC Low Density)
3D model M16D (16-Pin Small Outline Package 1.27 mm Pitch)
signal-integrity model MM74HC4052SJ
pins: 1 Y0 (io), 2 Y2 (io), 3 Y (io), 4 Y3 (io), 5 Y1 (io), 6 ~{EN} (in), 7 VEE (power), 8 GND (power), 9 B (in), 10 A (in), 11 X3 (io), 12 X0 (io), 13 X (io), 14 X1 (io), 15 X2 (io), 16 VCC (power)

## MM74HC4052WM
designator U?
Dual 4-Channel Analog Multiplexer
footprint M16B_N (SOIC, 16-Leads, Body 10.3x7.5mm, Pitch 1.27mm, IPC Medium Density)
footprint M16B_L (SOIC, 16-Leads, Body 10.3x7.5mm, Pitch 1.27mm, IPC High Density)
footprint M16B_M (SOIC, 16-Leads, Body 10.3x7.5mm, Pitch 1.27mm, IPC Low Density)
3D model M16B (16-Pin Small Outline Integrated Circuit 1.27 mm Pitch)
signal-integrity model MM74HC4052WM
pins: 1 Y0 (io), 2 Y2 (io), 3 Y (io), 4 Y3 (io), 5 Y1 (io), 6 ~{EN} (in), 7 VEE (power), 8 GND (power), 9 B (in), 10 A (in), 11 X3 (io), 12 X0 (io), 13 X (io), 14 X1 (io), 15 X2 (io), 16 VCC (power)

## MM74HC4053M
designator U?
Triple 2-Channel Analog Multiplexer
footprint M16A_N (SOIC, 16-Leads, Body 9.9x3.9mm, Pitch 1.27mm, IPC Medium Density)
footprint M16A_L (SOIC, 16-Leads, Body 9.9x3.9mm, Pitch 1.27mm, IPC High Density)
footprint M16A_M (SOIC, 16-Leads, Body 9.9x3.9mm, Pitch 1.27mm, IPC Low Density)
3D model M16A (16-Pin Small Outline Integrated Circuit 1.27 mm Pitch)
signal-integrity model MM74HC4053M
pins: 1 Y1 (io), 2 Y0 (io), 3 Z1 (io), 4 Z (io), 5 Z0 (io), 6 ~{EN} (in), 7 VEE (power), 8 GND (power), 9 C (in), 10 B (in), 11 A (in), 12 X0 (io), 13 X1 (io), 14 X (io), 15 Y (io), 16 VCC (power)

## MM74HC4053MTC
designator U?
Triple 2-Channel Analog Multiplexer
footprint MTC16_N (TSOP, 16-Leads, Body 5x4.4mm, Pitch 0.65mm, IPC Medium Density)
footprint MTC16_L (TSOP, 16-Leads, Body 5x4.4mm, Pitch 0.65mm, IPC High Density)
footprint MTC16_M (TSOP, 16-Leads, Body 5x4.4mm, Pitch 0.65mm, IPC Low Density)
3D model MTC16 (16-Pin Thin Small Outline Package 0.65 mm Pitch)
signal-integrity model MM74HC4053MTC
pins: 1 Y1 (io), 2 Y0 (io), 3 Z1 (io), 4 Z (io), 5 Z0 (io), 6 ~{EN} (in), 7 VEE (power), 8 GND (power), 9 C (in), 10 B (in), 11 A (in), 12 X0 (io), 13 X1 (io), 14 X (io), 15 Y (io), 16 VCC (power)

## MM74HC4053N
designator U?
Triple 2-Channel Analog Multiplexer
footprint N16E (DIP, 16-Leads, Row Spacing 7.62mm, Pitch 2.54mm, Body 19.3x6.35mm)
3D model N16E (DIP, 16-Pin, Row Spacing 7.62 mm, Pitch 2.54 mm)
signal-integrity model MM74HC4053N
pins: 1 Y1 (io), 2 Y0 (io), 3 Z1 (io), 4 Z (io), 5 Z0 (io), 6 ~{EN} (in), 7 VEE (power), 8 GND (power), 9 C (in), 10 B (in), 11 A (in), 12 X0 (io), 13 X1 (io), 14 X (io), 15 Y (io), 16 VCC (power)

## MM74HC4053SJ
designator U?
Triple 2-Channel Analog Multiplexer
footprint M16D_N (SOP, 16-Leads, Body 10.1x5.3mm, Pitch 1.27mm, IPC Medium Density)
footprint M16D_L (SOP, 16-Leads, Body 10.1x5.3mm, Pitch 1.27mm, IPC High Density)
footprint M16D_M (SOP, 16-Leads, Body 10.1x5.3mm, Pitch 1.27mm, IPC Low Density)
3D model M16D (16-Pin Small Outline Package 1.27 mm Pitch)
signal-integrity model MM74HC4053SJ
pins: 1 Y1 (io), 2 Y0 (io), 3 Z1 (io), 4 Z (io), 5 Z0 (io), 6 ~{EN} (in), 7 VEE (power), 8 GND (power), 9 C (in), 10 B (in), 11 A (in), 12 X0 (io), 13 X1 (io), 14 X (io), 15 Y (io), 16 VCC (power)

## MM74HC4053WM
designator U?
Triple 2-Channel Analog Multiplexer
footprint M16B_N (SOIC, 16-Leads, Body 10.3x7.5mm, Pitch 1.27mm, IPC Medium Density)
footprint M16B_L (SOIC, 16-Leads, Body 10.3x7.5mm, Pitch 1.27mm, IPC High Density)
footprint M16B_M (SOIC, 16-Leads, Body 10.3x7.5mm, Pitch 1.27mm, IPC Low Density)
3D model M16B (16-Pin Small Outline Integrated Circuit 1.27 mm Pitch)
signal-integrity model MM74HC4053WM
pins: 1 Y1 (io), 2 Y0 (io), 3 Z1 (io), 4 Z (io), 5 Z0 (io), 6 ~{EN} (in), 7 VEE (power), 8 GND (power), 9 C (in), 10 B (in), 11 A (in), 12 X0 (io), 13 X1 (io), 14 X (io), 15 Y (io), 16 VCC (power)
